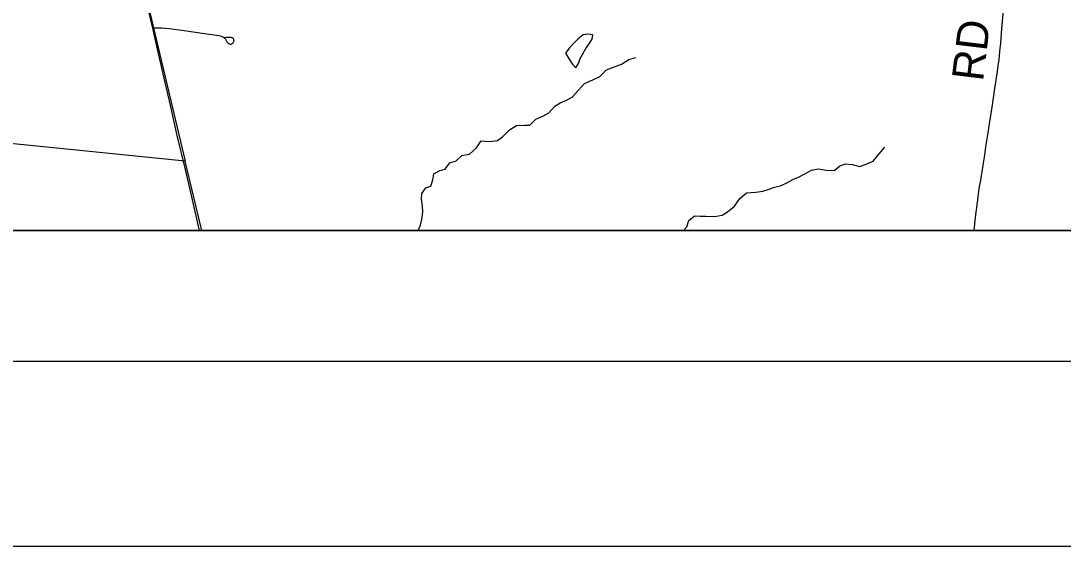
# Model space of a CAD drawing. Extents: x 0 to 1101, y 0 to 440.
# Drawn here: x 356 to 412.5, y 0 to 28.5 of the extents above; entities that cross this region are included whole.
import ezdxf

# ---------------------------------------------------------------- set-up
doc = ezdxf.new("R2010")
doc.units = 0
for name, color, linetype in [('Default', 7, 'Continuous'), ('GM_X_County_Road', 7, 'Continuous'), ('GM_X_Minor_Lake', 7, 'Continuous'), ('GM_X_Minor_River', 7, 'Continuous'), ('GM_X_Section', 7, 'Continuous'), ('GM_X_State_Route', 7, 'Continuous'), ('GM_X_Township_Road', 7, 'Continuous'), ('GM_X_Township_Road_Text', 7, 'Continuous'), ('SH_Border', 7, 'Continuous'), ('SH_Cut_Line', 7, 'Continuous'), ('SH_Text', 7, 'Continuous')]:
    doc.layers.add(name, color=color, linetype=linetype)

msp = doc.modelspace()

# ---------------------------------------------------------------- linework, layer by layer
at = {"layer": 'Default'}
msp.add_lwpolyline([(350.987, 17.107), (365.835, 17.107), (364.939, 20.863), (351.527, 22.22)], close=True, dxfattribs=at)
at = {"layer": 'GM_X_County_Road'}
msp.add_lwpolyline([(350.892, 17.107), (492.757, 17.107), (494.967, 38.564), (486.494, 39.335), (480.73, 40.036), (456.87, 41.812), (429.195, 44.697), (407.625, 46.582), (393.244, 47.835), (358.093, 49.313), (354.24, 49.634), (351.415, 22.133)], close=True, dxfattribs=at)
at = {"layer": 'GM_X_Minor_Lake'}
for points in [[(386.852, 27.733), (386.73, 27.749), (386.48, 27.706), (386.217, 27.492), (385.942, 27.221), (385.725, 26.984), (385.53, 26.723)], [(385.53, 26.723), (385.731, 26.392), (385.888, 26.129), (386.091, 25.923), (386.24, 26.195), (386.322, 26.422), (386.471, 26.682), (386.633, 26.965), (386.805, 27.225), (386.966, 27.474), (387.002, 27.713), (386.852, 27.733)]]:
    msp.add_lwpolyline(points, dxfattribs=at)
at = {"layer": 'GM_X_Minor_River'}
for points in [[(377.545, 17.107), (377.667, 17.401), (377.749, 17.696), (377.809, 18.094), (377.777, 18.447), (377.735, 18.811), (377.738, 19.118), (377.956, 19.424), (378.24, 19.501), (378.334, 19.853), (378.405, 20.171), (378.724, 20.362), (379.008, 20.428), (379.261, 20.778), (379.614, 20.878), (379.911, 21.171), (380.332, 21.236), (380.698, 21.586), (380.962, 21.971), (381.415, 21.922), (381.836, 21.986), (382.121, 22.178), (382.488, 22.561), (382.875, 22.797), (383.307, 22.805), (383.602, 22.814), (383.923, 23.142), (384.298, 23.309), (384.618, 23.477), (384.95, 23.85), (385.235, 24.019), (385.577, 24.164), (385.885, 24.332), (386.228, 24.705), (386.56, 25.077), (387.005, 25.279), (387.392, 25.458), (387.747, 25.807), (388.123, 25.952), (388.555, 26.12), (388.954, 26.367), (389.341, 26.477)], [(391.911, 17.107), (392.092, 17.299), (392.208, 17.651), (392.517, 17.899), (392.834, 17.885), (393.13, 17.882), (393.595, 17.867), (394.004, 17.944), (394.289, 18.112), (394.678, 18.428), (394.965, 18.846), (395.33, 19.139), (395.83, 19.181), (396.205, 19.235), (396.49, 19.323), (396.831, 19.446), (397.161, 19.534), (397.549, 19.713), (397.834, 19.87), (398.141, 20.004), (398.437, 20.15), (398.837, 20.374), (399.212, 20.439), (399.631, 20.379), (400.062, 20.353), (400.359, 20.59), (400.667, 20.712), (401.041, 20.675), (401.46, 20.581), (401.836, 20.715), (402.178, 20.871), (402.499, 21.255), (402.819, 21.617)]]:
    msp.add_lwpolyline(points, dxfattribs=at)
at = {"layer": 'GM_X_Section'}
msp.add_lwpolyline([(362.761, 30.005), (364.939, 20.863), (351.527, 22.22), (354.738, 51.418), (357.612, 51.067)], close=True, dxfattribs=at)
at = {"layer": 'GM_X_State_Route'}
msp.add_lwpolyline([(365.714, 17.107), (365.234, 19.163), (364.948, 20.416), (364.508, 22.247), (364.133, 23.902), (363.85, 25.119), (363.487, 26.699), (363.276, 27.646), (363.18, 28.076), (363.118, 28.355), (362.821, 29.625)], dxfattribs=at)
at = {"layer": 'GM_X_Township_Road'}
for points in [[(407.645, 17.107), (407.728, 17.802), (407.876, 19.052), (407.909, 19.261), (407.945, 19.493), (408.002, 19.814), (408.047, 20.075), (408.084, 20.285), (408.14, 20.647), (408.221, 21.187), (408.269, 21.491), (408.324, 21.851), (408.392, 22.293), (408.483, 22.882), (408.625, 23.784), (408.772, 24.803), (408.907, 25.72), (408.954, 26.028), (408.998, 26.367), (409.026, 26.591), (409.048, 26.83), (409.087, 27.259), (409.153, 28.056), (409.245, 29.044)], [(363.18, 28.076), (363.28, 28.083), (363.397, 28.091), (363.48, 28.095), (363.574, 28.096), (363.677, 28.093), (364.067, 28.052), (364.88, 27.945), (365.986, 27.786), (366.761, 27.666), (366.874, 27.641), (366.927, 27.623), (366.965, 27.606), (367.001, 27.584), (367.032, 27.563), (367.063, 27.533), (367.088, 27.505), (367.11, 27.473), (367.13, 27.438), (367.191, 27.328), (367.205, 27.309), (367.218, 27.294), (367.251, 27.266), (367.28, 27.244), (367.307, 27.229), (367.338, 27.217), (367.37, 27.21), (367.396, 27.209), (367.417, 27.21), (367.441, 27.214), (367.463, 27.221), (367.49, 27.235), (367.516, 27.256), (367.54, 27.282), (367.556, 27.308), (367.569, 27.339), (367.577, 27.369), (367.579, 27.396), (367.577, 27.417), (367.573, 27.444), (367.565, 27.464), (367.557, 27.484), (367.542, 27.504), (367.528, 27.518), (367.507, 27.534), (367.49, 27.544), (367.465, 27.553), (367.432, 27.563), (367.387, 27.57), (367.35, 27.571), (367.309, 27.571), (367.261, 27.569), (367.164, 27.561), (367.054, 27.553)]]:
    msp.add_lwpolyline(points, dxfattribs=at)
at = {"layer": 'SH_Border'}
msp.add_lwpolyline([(30, 430), (670, 430), (670, 10), (30, 10)], close=True, dxfattribs=at)
at = {"layer": 'SH_Cut_Line'}
msp.add_lwpolyline([(0, 0), (680, 0), (680, 440), (0, 440)], close=True, dxfattribs=at)
msp.add_lwpolyline([(131, 17.107), (539, 17.107)], dxfattribs=at)
at = {"layer": 'SH_Text'}
msp.add_lwpolyline([(131, 425.107), (539, 425.107), (539, 17.107), (131, 17.107)], close=True, dxfattribs=at)

# ---------------------------------------------------------------- texts
at = {"layer": 'GM_X_Township_Road_Text'}
msp.add_text('RD', height=1.7045, rotation=83.1181, dxfattribs=at).set_placement((408.127, 25.148))

doc.saveas('drawing.dxf')
